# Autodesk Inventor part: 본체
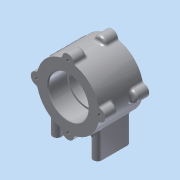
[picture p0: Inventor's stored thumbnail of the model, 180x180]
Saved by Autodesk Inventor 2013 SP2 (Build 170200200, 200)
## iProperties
Created: 2015-03
Part Number: 본체
Material: 알루미늄 6061
Document SubType Name: Modeling
Designer: dgall
Density: 2.71 g/cm^3
Mass: 450.777 g
Surface Area: 332.735 cm^2
Volume: 166.339 cm^3
Author: dgall
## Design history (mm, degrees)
sketch "스케치1"
  geometry: C1 r 37 at (0, 0); C2 r 21 at (0, 0); C3 r 23.5 at (0, 0); 1 further point
  constraints: 3 centre point, 3 coincident
  dimensions: "d0" = 74 diameter of C1; "d3" = 42 diameter of C2; "d6" = 47 diameter of C3
extrude "돌출1" new body sketch "스케치1" distance "d1" = 52; taper "d2" = 0 deg
extrude "돌출2" cut sketch "스케치1" stored distance "d4" = 0; taper "d5" = 0 deg
extrude "돌출3" cut sketch "스케치1" distance "d7" = 22; taper "d8" = 0 deg
node "작업 평면1"
node "작업 평면2"
sketch "스케치2"
  geometry: L1 (19, -11)-(29, -11); L2 (29, -11)-(29, -41); L3 (29, -41)-(19, -41); L4 (19, -41)-(19, -11); L5 (37, 0)-(37, -52) reference; A1 r 5 centre (24, -11) between (29, -11) and (19, -11); A2 r 5 centre (24, -41) between (19, -41) and (29, -41); 3 further points
  constraints: 8 end point, 4 point on circle, 4 tangent, 2 centre point, 2 midpoint, 2 parallel, 1 horizontal, 1 horizontal alignment, 1 perpendicular
  dimensions: "d10" = 10 distance between parallel lines of L2 L4; "d12" = 40 dimension on A2 A1; "d13" = 24 horizontal distance of point (0, 0) A1.centre
extrude "돌출4" join sketch "스케치2" stored distance "d14" = 56; taper "d15" = 0 deg
fillet "모깎기1" dims "d16" = 3
sketch "스케치3"
  geometry: C1 r 23.5 at (0, 0) reference; C2 r 7 at (0, -37); 2 further points
  constraints: 2 vertical alignment, 1 centre point, 1 coincident, 1 other
  dimensions: "d19" = 7 radius of C2
extrude "돌출5" join sketch "스케치3" distance "d21" = 15; taper "d22" = 0 deg
hole "구멍1" sketch "스케치3" diameter "d23" = 3.242; stored, may be unused: countersink angle "d27" = 90 deg, drill point angle "d29" = 118 deg; dims "d24" = 8, "d25" = 4, "d26" = 2, "d28" = 11
fillet "모깎기2" dims "d30" = 3
fillet "모깎기3" dims "d31" = 3
node "작업 평면3"
sketch "스케치4"
  geometry: L1 (19, 11)-(19, 41) reference; L2 (29, 41)-(29, 11) reference; A1 r 5 centre (-24, 41) between (-19, 41) and (-29, 41) reference; A2 r 5 centre (-24, 11) between (-29, 11) and (-19, 11) reference; A3 r 5 centre (24, 11) between (19, 11) and (29, 11) reference; A4 r 5 centre (24, 41) between (29, 41) and (19, 41) reference; 5 further points
  constraints: 4 coincident
hole "구멍2" sketch "스케치4" at (24, 11), (24, 41), (-24, 11), (-24, 41) diameter "d35" = 4.134; stored, may be unused: countersink angle "d39" = 90 deg, drill point angle "d41" = 118 deg; dims "d36" = 6, "d37" = 4, "d38" = 2, "d40" = 8
fillet "모깎기4" dims "d42" = 0.3
chamfer "모따기1" distance "d43" = 1; stored, may be unused: second distance "d44" = 2, angle "d45" = 45 deg
sketch "스케치5"
  geometry: L1 (0, 0)-(44, 0); L2 (0, 0)-(26.163, -26.163); L3 (7.84, -36.16)-(44, 0); A1 r 37 centre (0, 0) between (9.104, -35.862) and (35.862, -9.104) reference; A2 r 7 centre (37, 0) between (38.239, -6.889) and (38.239, 6.889) reference
  constraints: 6 end point, 3 point on circle, 1 horizontal
  dimensions: "d46" = 45 deg angle of L1 L2; "d47" = 90 deg angle of L2 L3
node "작업 평면5"
  node "작업 평면4"
sketch "스케치6"
  geometry: L1 (-18.921, -52)-(18.921, -52) reference; 2 further points
  constraints: 1 vertical alignment, 1 other
  dimensions: "d49" = 26 distance from line of L1 point (0, -26)
feature "엠보싱1" sketch "스케치6" dims "d50" = 0.5, "d51" = 0
node "솔리드1"
mirror "대칭1"
mirror "대칭2"
pattern_circular "원형 패턴1" dims "d33" = 360 deg
mirror "대칭3"
node "투영된 루프1"
other parameters: "d9" = 56, "d48" = 90 deg
